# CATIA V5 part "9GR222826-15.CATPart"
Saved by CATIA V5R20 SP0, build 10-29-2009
Part number: 9GR222826-15
Revision: ANY
Definition: UNKNOWN
Nomenclature: 9GR222826-15
Source: Unknown
Bounding box of the stored display mesh (mm): x -12.979 to 12.803, y -23 to 5, z -13 to 13
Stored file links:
  C:\Users\Utente\Desktop\IO LAVORO\3D X SITO CF\CUMSA\3D files GR\GR 222826-15\9GR222826-15.CATPart
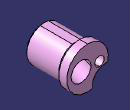
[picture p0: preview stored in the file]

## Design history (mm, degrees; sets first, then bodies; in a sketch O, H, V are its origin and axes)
Body1 "Cortar-Extruir7" (main body)
  Solid1: solid without history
